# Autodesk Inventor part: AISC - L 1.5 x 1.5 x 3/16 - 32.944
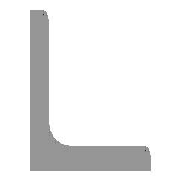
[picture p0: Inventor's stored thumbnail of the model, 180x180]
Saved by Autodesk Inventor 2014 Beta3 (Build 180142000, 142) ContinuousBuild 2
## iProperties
_CCFamilyMember: 5
_CCFamilyDisplayName: ANSI L (Equal angles) - Angle Steel
_FrameMemberDoc: Frame Member File
_Version: 15.0.0
_GetPNFromCC: 1
Created: 2010-11
Part Number: AISC - L 1.5 x 1.5 x 3/16 - 32.944
Material: Steel, Mild
Description: Angle Steel
Document SubType Name: Modeling
Standard: ANSI
Designer: Beta-8540w
Standards Organization: ANSI
Language: en-US
Size Designation: L 1.5 x 1.5 x 3/16
Categories: <MemberInstance><Categories><Category DisplayName="Structural Shapes" InternalName="089c4875-fa83-4c05-b084-43b9cc11f5ed" Mnemonic="GRDR"><CategoryParameter Dis
Stock Number: L 1.5 x 1.5 x 3/16
Density: 7.86 g/cm^3
Appearance: Steel
G_L: 32.944 in
G_W: 1.500 in
G_H: 1.500 in
IsCustomPart: 1
Author: Beta-8540w
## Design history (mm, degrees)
node "Start plane"
node "End plane"
sketch "Sketch"
  geometry: L1 (38.1, 0)-(0, 0); L2 (0, 0)-(0, 38.1); L3 (0, 38.1)-(2.476, 38.1); L4 (4.762, 35.814)-(4.762, 9.589); L5 (9.588, 4.763)-(35.814, 4.763); L6 (38.1, 2.477)-(38.1, 0); L7 (0, -11.041)-(0, 31.538); L8 (-11.041, 0)-(31.538, 0); L9 (0, 48.496)-(0, -20.964) reference; L10 (-20.964, 0)-(48.496, 0) reference; A1 r 4.826 centre (9.588, 9.589) between (4.762, 9.589) and (9.588, 4.763); A2 r 2.286 centre (2.476, 35.814) between (4.762, 35.814) and (2.476, 38.1); A3 r 2.286 centre (35.814, 2.477) between (38.1, 2.477) and (35.814, 4.763); 3 further points
  constraints: 16 end point, 6 point on circle, 6 point on line, 6 tangent, 4 parallel, 3 centre point, 2 collinear, 1 equal radius, 1 horizontal, 1 perpendicular
  dimensions: "d0" = 38.1 distance between parallel lines of L6 L2 (= G_H); "d1" = 38.1 distance between parallel lines of L3 L1 (= G_H); "d2" = 4.7625 distance between parallel lines of L2 L4 (= G_T); "d3" = 4.7625 distance between parallel lines of L1 L5 (= G_T); "d10" = 0 distance between parallel lines of L7 L2 (computed from ex); "d11" = 0 distance between parallel lines of L8 L1 (computed from d10); "d14" = 4.826 radius of A1 (= G_IR); "d15" = 2.286 radius of A2 (= G_ER)
extrude "Body" new body sketch "Sketch" stored distance "d4" = 836.76542 (= G_L); taper "d5" = 0 deg
node "Driven Length"
  sketch "Sketch3"
    geometry: L1 (0, 0)-(10, 0) reference
    constraints: 2 end point, 1 horizontal
  workplane "Work Plane3"
  sketch "Sketch4"
    geometry: L1 (-2, 0)-(12, 0) reference; L2 (-2, 836.765)-(12, 836.765) reference
    dimensions: "d17" = 836.76542 distance between parallel lines of L1 L2 (derived)
body "Solid1"
other parameters: "G_H" = 38.1 [user parameter; used in 2 equation terms], "G_T" = 4.7625 [user parameter; used in 2 equation terms], "G_ER" = 2.286 [user parameter; used in 1 equation term], "G_IR" = 4.826 [user parameter; used in 1 equation term], "G_L" = 836.76542 (= d17) [user parameter; used in 1 equation term], "ex" = 0 [user parameter; used in 1 equation term], "G_OFFSET_START" = 0 [user parameter; used in 1 equation term], "G_OFFSET_END" = 0 [user parameter; used in 1 equation term], "d12" = 0 (computed from G_OFFSET_START), "d13" = 836.76542 (= G_OFFSET_END + B_L), "B_L" = 836.76542 [user parameter; used in 1 equation term], "d16" = 90 deg, "MAS" = 0.26787 [user parameter]
